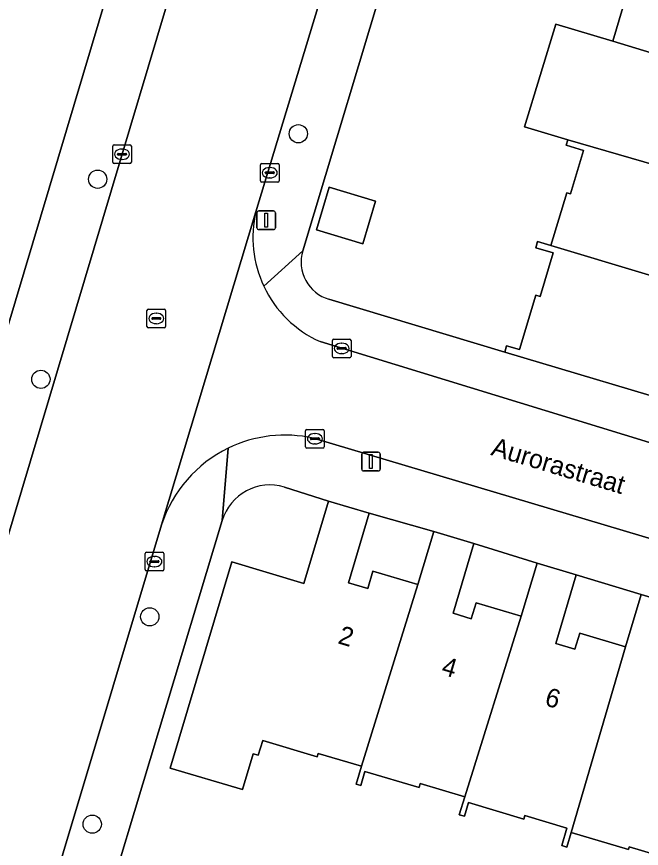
# Model space of a CAD drawing. Extents: x 162184 to 163154, y 385507 to 386516.
# Drawn here: x 162544.83 to 162578.31, y 386044.74 to 386089.33 of the extents above; entities that cross this region are included whole.
import ezdxf

# ---------------------------------------------------------------- set-up
doc = ezdxf.new("R2010")
doc.units = 0
for name, color, linetype in [('IMGEO_Boom', 7, 'Continuous'), ('IMGEO_Erf', 7, 'Continuous'), ('IMGEO_Groenvoorziening', 7, 'Continuous'), ('IMGEO_Kolk', 7, 'Continuous'), ('IMGEO_Lichtmast', 7, 'Continuous'), ('IMGEO_Openbare_ruimte_label', 7, 'Continuous'), ('IMGEO_Pand', 7, 'Continuous'), ('IMGEO_Pand_nummerreeks', 7, 'Continuous'), ('IMGEO_Rijbaan_lokaal_gesloten', 7, 'Continuous'), ('IMGEO_Rijbaan_lokaal_open', 7, 'Continuous'), ('IMGEO_Rioolput', 7, 'Continuous'), ('IMGEO_Voetpad_open', 7, 'Continuous')]:
    doc.layers.add(name, color=color, linetype=linetype)

msp = doc.modelspace()

# ---------------------------------------------------------------- linework, layer by layer
at = {"layer": 'IMGEO_Boom'}
for centre in [(162559.923, 386083.051), (162549.169, 386080.614), (162546.127, 386069.889), (162551.963, 386057.155), (162548.879, 386046.038)]:
    msp.add_circle(centre, 0.489, dxfattribs=at)
at = {"layer": 'IMGEO_Erf'}
for points in [[(162574.588, 386124.721), (162560.164, 386076.774)], [(162561.564, 386074.178), (162570.985, 386071.35), (162571.086, 386071.69), (162571.785, 386071.481), (162572.658, 386074.403), (162572.883, 386074.335), (162573.577, 386076.659), (162572.647, 386076.937), (162572.749, 386077.279), (162573.464, 386077.066), (162574.309, 386079.892), (162574.519, 386079.829), (162575.214, 386082.154), (162574.286, 386082.432), (162574.373, 386082.723), (162572.052, 386083.416), (162573.719, 386088.923), (162576.772, 386088.011), (162577.661, 386090.987)], [(162579.822, 386044.188), (162577.661, 386044.833), (162577.614, 386044.676), (162574.55, 386045.591), (162574.316, 386044.81), (162574.043, 386044.892), (162574.323, 386045.829), (162572.071, 386046.501), (162572.015, 386046.314), (162569.041, 386047.202), (162568.822, 386046.467), (162568.552, 386046.548), (162568.84, 386047.513), (162566.462, 386048.224), (162566.397, 386048.005), (162563.496, 386048.871), (162563.267, 386048.105), (162563.022, 386048.178), (162563.309, 386049.141), (162560.986, 386049.835), (162560.931, 386049.653), (162558.014, 386050.525), (162557.779, 386049.736), (162557.501, 386049.819), (162556.925, 386047.891), (162553.064, 386049.045), (162556.367, 386060.102), (162560.228, 386058.948), (162561.544, 386063.355), (162559.189, 386064.113)], [(162555.845, 386062.31), (162549.021, 386039.652), (162548.964, 386039.426), (162548.927, 386039.196), (162548.911, 386038.964), (162548.916, 386038.731), (162548.942, 386038.499), (162548.988, 386038.271), (162549.054, 386038.048), (162549.14, 386037.831), (162549.245, 386037.623), (162549.369, 386037.426), (162549.509, 386037.24), (162549.665, 386037.067), (162549.837, 386036.909), (162550.021, 386036.767), (162550.218, 386036.642), (162550.425, 386036.536), (162550.64, 386036.448), (162550.863, 386036.379), (162550.925, 386036.364), (162601.617, 386024.622)]]:
    msp.add_lwpolyline(points, dxfattribs=at)
for points in [[(162563.38, 386077.154), (162560.899, 386077.895), (162561.583, 386080.183), (162564.063, 386079.442)], [(162563.726, 386062.704), (162562.615, 386058.983), (162563.646, 386058.675), (162563.925, 386059.608), (162566.334, 386058.888), (162567.184, 386061.729)], [(162569.337, 386061.086), (162568.22, 386057.344), (162569.191, 386057.054), (162569.447, 386057.91), (162571.874, 386057.185), (162572.722, 386060.027)], [(162574.821, 386059.4), (162573.725, 386055.732), (162574.748, 386055.426), (162575.003, 386056.28), (162577.455, 386055.547), (162578.295, 386058.358)]]:
    msp.add_lwpolyline(points, close=True, dxfattribs=at)
for centre, radius, start, end in [((162562.154, 386076.172), 2.079, 163.1674, 253.5078), ((162558.42, 386061.536), 2.689, 73.3908, 163.274)]:
    msp.add_arc(centre, radius, start, end, dxfattribs=at)
at = {"layer": 'IMGEO_Groenvoorziening'}
msp.add_lwpolyline([(162540.262, 386059.084), (162551.525, 386096.722), (162551.592, 386096.979), (162551.635, 386097.241), (162551.656, 386097.506), (162551.652, 386097.772), (162551.624, 386098.036), (162551.573, 386098.297), (162551.499, 386098.552), (162551.403, 386098.8), (162551.285, 386099.038), (162551.146, 386099.264), (162550.987, 386099.477), (162550.81, 386099.675), (162550.616, 386099.857), (162550.406, 386100.02), (162550.183, 386100.164), (162549.948, 386100.288), (162549.702, 386100.39), (162549.449, 386100.47), (162549.189, 386100.526), (162549.072, 386100.544), (162535.156, 386102.359)], dxfattribs=at)
at = {"layer": 'IMGEO_Kolk'}
for p, q in [((162550.051, 386082.453), (162550.903, 386082.453)), ((162549.976, 386081.527), (162549.976, 386082.379)), ((162550.464, 386082.233), (162550.489, 386082.233)), ((162550.977, 386082.379), (162550.977, 386081.527)), ((162550.235, 386081.947), (162550.235, 386081.959)), ((162550.673, 386081.91), (162550.275, 386081.91)), ((162550.278, 386081.996), (162550.676, 386081.996)), ((162550.487, 386081.673), (162550.462, 386081.673)), ((162550.719, 386081.959), (162550.719, 386081.947)), ((162550.903, 386081.453), (162550.051, 386081.453)), ((162557.895, 386080.534), (162557.895, 386081.386)), ((162557.97, 386081.46), (162558.822, 386081.46)), ((162558.383, 386081.24), (162558.408, 386081.24)), ((162558.896, 386081.386), (162558.896, 386080.534)), ((162558.154, 386080.954), (162558.154, 386080.966)), ((162558.592, 386080.917), (162558.194, 386080.917)), ((162558.197, 386081.003), (162558.595, 386081.003)), ((162558.406, 386080.68), (162558.381, 386080.68)), ((162558.638, 386080.966), (162558.638, 386080.954)), ((162558.822, 386080.46), (162557.97, 386080.46)), ((162561.749, 386071.119), (162561.749, 386071.971)), ((162561.824, 386072.045), (162562.676, 386072.045)), ((162562.237, 386071.825), (162562.262, 386071.825)), ((162562.75, 386071.971), (162562.75, 386071.119)), ((162562.008, 386071.539), (162562.008, 386071.551)), ((162562.446, 386071.502), (162562.048, 386071.502)), ((162562.051, 386071.588), (162562.449, 386071.588)), ((162562.492, 386071.551), (162562.492, 386071.539)), ((162562.676, 386071.045), (162561.824, 386071.045)), ((162562.26, 386071.265), (162562.235, 386071.265)), ((162560.311, 386066.276), (162560.311, 386067.128)), ((162560.386, 386067.202), (162561.238, 386067.202)), ((162560.799, 386066.982), (162560.824, 386066.982)), ((162561.312, 386067.128), (162561.312, 386066.276)), ((162560.57, 386066.696), (162560.57, 386066.708)), ((162561.008, 386066.659), (162560.61, 386066.659)), ((162560.613, 386066.745), (162561.011, 386066.745)), ((162560.822, 386066.422), (162560.797, 386066.422)), ((162561.054, 386066.708), (162561.054, 386066.696)), ((162561.238, 386066.202), (162560.386, 386066.202)), ((162551.789, 386060.615), (162552.641, 386060.615)), ((162551.714, 386059.689), (162551.714, 386060.541)), ((162552.016, 386060.158), (162552.414, 386060.158)), ((162552.202, 386060.395), (162552.227, 386060.395)), ((162552.715, 386060.541), (162552.715, 386059.689)), ((162551.973, 386060.109), (162551.973, 386060.121)), ((162552.411, 386060.072), (162552.013, 386060.072)), ((162552.225, 386059.835), (162552.2, 386059.835)), ((162552.457, 386060.121), (162552.457, 386060.109)), ((162552.641, 386059.615), (162551.789, 386059.615))]:
    msp.add_line(p, q, dxfattribs=at)
for points in [[(162550.051, 386082.453), (162550.903, 386082.453)], [(162549.976, 386081.527), (162549.976, 386082.379)], [(162550.977, 386082.379), (162550.977, 386081.527)], [(162550.903, 386081.453), (162550.051, 386081.453)], [(162557.895, 386080.534), (162557.895, 386081.386)], [(162557.97, 386081.46), (162558.822, 386081.46)], [(162558.896, 386081.386), (162558.896, 386080.534)], [(162558.822, 386080.46), (162557.97, 386080.46)], [(162561.749, 386071.119), (162561.749, 386071.971)], [(162561.824, 386072.045), (162562.676, 386072.045)], [(162562.75, 386071.971), (162562.75, 386071.119)], [(162562.676, 386071.045), (162561.824, 386071.045)], [(162560.311, 386066.276), (162560.311, 386067.128)], [(162560.386, 386067.202), (162561.238, 386067.202)], [(162561.312, 386067.128), (162561.312, 386066.276)], [(162561.238, 386066.202), (162560.386, 386066.202)], [(162551.789, 386060.615), (162552.641, 386060.615)], [(162551.714, 386059.689), (162551.714, 386060.541)], [(162552.715, 386060.541), (162552.715, 386059.689)], [(162552.641, 386059.615), (162551.789, 386059.615)]]:
    msp.add_lwpolyline(points, dxfattribs=at)
for centre, radius, start, end in [((162550.053, 386082.377), 0.0765, 91.552, 178.448), ((162550.053, 386082.377), 0.0765, 91.552, 178.448), ((162550.901, 386082.377), 0.0765, 1.552, 88.448), ((162550.901, 386082.377), 0.0765, 1.552, 88.448), ((162550.275, 386081.956), 0.0403, 85.8775, 175.7526), ((162550.272, 386081.946), 0.0366, 178.938, 274.7102), ((162550.676, 386081.953), 0.043, 264.8664, 352.4533), ((162550.68, 386081.958), 0.0386, 1.7309, 96.639), ((162550.053, 386081.529), 0.0765, 181.552, 268.448), ((162550.053, 386081.529), 0.0765, 181.552, 268.448), ((162550.901, 386081.529), 0.0765, 271.552, 358.448), ((162550.901, 386081.529), 0.0765, 271.552, 358.448), ((162557.972, 386081.384), 0.0765, 91.552, 178.448), ((162557.972, 386081.384), 0.0765, 91.552, 178.448), ((162558.82, 386081.384), 0.0765, 1.552, 88.448), ((162558.82, 386081.384), 0.0765, 1.552, 88.448), ((162558.194, 386080.963), 0.0403, 85.8775, 175.7526), ((162558.191, 386080.953), 0.0366, 178.938, 274.7102), ((162558.595, 386080.96), 0.043, 264.8664, 352.4533), ((162558.599, 386080.965), 0.0386, 1.7309, 96.639), ((162557.972, 386080.536), 0.0765, 181.552, 268.448), ((162557.972, 386080.536), 0.0765, 181.552, 268.448), ((162558.82, 386080.536), 0.0765, 271.552, 358.448), ((162558.82, 386080.536), 0.0765, 271.552, 358.448), ((162561.826, 386071.969), 0.0765, 91.552, 178.448), ((162561.826, 386071.969), 0.0765, 91.552, 178.448), ((162562.674, 386071.969), 0.0765, 1.552, 88.448), ((162562.674, 386071.969), 0.0765, 1.552, 88.448), ((162562.048, 386071.548), 0.0403, 85.8775, 175.7526), ((162562.045, 386071.538), 0.0366, 178.938, 274.7102), ((162562.449, 386071.545), 0.043, 264.8664, 352.4533), ((162562.453, 386071.55), 0.0386, 1.7309, 96.639), ((162561.826, 386071.121), 0.0765, 181.552, 268.448), ((162561.826, 386071.121), 0.0765, 181.552, 268.448), ((162562.674, 386071.121), 0.0765, 271.552, 358.448), ((162562.674, 386071.121), 0.0765, 271.552, 358.448), ((162560.388, 386067.126), 0.0765, 91.552, 178.448), ((162560.388, 386067.126), 0.0765, 91.552, 178.448), ((162561.236, 386067.126), 0.0765, 1.552, 88.448), ((162561.236, 386067.126), 0.0765, 1.552, 88.448), ((162560.61, 386066.705), 0.0403, 85.8775, 175.7526), ((162560.607, 386066.695), 0.0366, 178.938, 274.7102), ((162561.011, 386066.702), 0.043, 264.8664, 352.4533), ((162561.015, 386066.707), 0.0386, 1.7309, 96.639), ((162560.388, 386066.278), 0.0765, 181.552, 268.448), ((162560.388, 386066.278), 0.0765, 181.552, 268.448), ((162561.236, 386066.278), 0.0765, 271.552, 358.448), ((162561.236, 386066.278), 0.0765, 271.552, 358.448), ((162551.791, 386060.539), 0.0765, 91.552, 178.448), ((162551.791, 386060.539), 0.0765, 91.552, 178.448), ((162552.639, 386060.539), 0.0765, 1.552, 88.448), ((162552.639, 386060.539), 0.0765, 1.552, 88.448), ((162552.013, 386060.118), 0.0403, 85.8775, 175.7526), ((162552.418, 386060.12), 0.0386, 1.7309, 96.639), ((162552.01, 386060.108), 0.0366, 178.938, 274.7102), ((162552.414, 386060.115), 0.043, 264.8664, 352.4533), ((162551.791, 386059.691), 0.0765, 181.552, 268.448), ((162551.791, 386059.691), 0.0765, 181.552, 268.448), ((162552.639, 386059.691), 0.0765, 271.552, 358.448), ((162552.639, 386059.691), 0.0765, 271.552, 358.448)]:
    msp.add_arc(centre, radius, start, end, dxfattribs=at)
for centre, major_axis, ratio, start_param, end_param in [((162550.463, 386081.953), (-0.387, 0.002), 0.722429, 4.712389, 7.853982), ((162550.488, 386081.953), (-0.39, 0.002), 0.717154, 1.570796, 4.712389), ((162558.382, 386080.96), (-0.387, 0.002), 0.722429, 4.712389, 7.853982), ((162558.407, 386080.96), (-0.39, 0.002), 0.717154, 1.570796, 4.712389), ((162562.236, 386071.545), (-0.387, 0.002), 0.722429, 4.712389, 7.853982), ((162562.261, 386071.545), (-0.39, 0.002), 0.717154, 1.570796, 4.712389), ((162560.798, 386066.702), (-0.387, 0.002), 0.722429, 4.712389, 7.853982), ((162560.823, 386066.702), (-0.39, 0.002), 0.717154, 1.570796, 4.712389), ((162552.201, 386060.115), (-0.387, 0.002), 0.722429, 4.712389, 7.853982), ((162552.226, 386060.115), (-0.39, 0.002), 0.717154, 1.570796, 4.712389)]:
    msp.add_ellipse(centre, major_axis=major_axis, ratio=ratio, start_param=start_param, end_param=end_param, dxfattribs=at)
at = {"layer": 'IMGEO_Lichtmast'}
for p, q in [((162557.807, 386078.913), (162558.597, 386078.913)), ((162558.597, 386078.913), (162557.807, 386078.913)), ((162557.707, 386078.013), (162557.707, 386078.813)), ((162557.707, 386078.813), (162557.707, 386078.013)), ((162558.697, 386078.813), (162558.697, 386078.013)), ((162558.697, 386078.013), (162558.697, 386078.813)), ((162558.597, 386077.913), (162557.807, 386077.913)), ((162557.807, 386077.913), (162558.597, 386077.913)), ((162563.42, 386065.973), (162564.21, 386065.973)), ((162564.21, 386065.973), (162563.42, 386065.973)), ((162563.32, 386065.073), (162563.32, 386065.873)), ((162563.32, 386065.873), (162563.32, 386065.073)), ((162564.31, 386065.873), (162564.31, 386065.073)), ((162564.31, 386065.073), (162564.31, 386065.873)), ((162564.21, 386064.973), (162563.42, 386064.973)), ((162563.42, 386064.973), (162564.21, 386064.973))]:
    msp.add_line(p, q, dxfattribs=at)
for points in [[(162558.127, 386078.788), (162558.277, 386078.788), (162558.277, 386078.038), (162558.127, 386078.038), (162558.127, 386078.788)], [(162563.74, 386065.848), (162563.89, 386065.848), (162563.89, 386065.098), (162563.74, 386065.098), (162563.74, 386065.848)]]:
    msp.add_lwpolyline(points, dxfattribs=at)
for centre, start, end in [((162557.807, 386078.813), 90, 180), ((162557.807, 386078.813), 90, 180), ((162558.597, 386078.813), 0, 90), ((162558.597, 386078.813), 360, 90), ((162557.807, 386078.013), 180, 270), ((162557.807, 386078.013), 180, 270), ((162558.597, 386078.013), 270, 0), ((162558.597, 386078.013), 270, 0), ((162563.42, 386065.873), 90, 180), ((162563.42, 386065.873), 90, 180), ((162564.21, 386065.873), 0, 90), ((162564.21, 386065.873), 360, 90), ((162563.42, 386065.073), 180, 270), ((162563.42, 386065.073), 180, 270), ((162564.21, 386065.073), 270, 0), ((162564.21, 386065.073), 270, 0)]:
    msp.add_arc(centre, 0.1, start, end, dxfattribs=at)
at = {"layer": 'IMGEO_Pand'}
for points in [[(162591.23, 386089.684), (162588.386, 386090.535), (162577.712, 386093.701), (162577.629, 386093.423), (162578.556, 386093.146), (162577.89, 386090.918), (162577.661, 386090.987), (162576.772, 386088.011), (162586.695, 386085), (162587.392, 386087.335), (162586.606, 386087.57), (162586.941, 386088.691), (162590.607, 386087.596)], [(162585.106, 386079.616), (162585.771, 386081.84), (162584.938, 386082.089), (162585.269, 386083.197), (162588.93, 386082.104), (162589.541, 386084.15), (162586.695, 386085), (162576.772, 386088.011), (162573.719, 386088.923), (162572.052, 386083.416), (162574.373, 386082.723)], [(162573.464, 386077.066), (162583.387, 386074.069), (162584.081, 386076.39), (162583.306, 386076.621), (162583.617, 386077.664), (162587.259, 386076.576), (162587.916, 386078.777), (162585.106, 386079.616), (162574.373, 386082.723), (162574.286, 386082.432), (162575.214, 386082.154), (162574.519, 386079.829), (162574.309, 386079.892)], [(162563.38, 386077.154), (162564.063, 386079.442), (162561.583, 386080.183), (162560.899, 386077.895)], [(162581.66, 386068.161), (162582.467, 386070.862), (162581.62, 386071.115), (162581.944, 386072.201), (162585.655, 386071.093), (162586.285, 386073.202), (162583.387, 386074.069), (162573.464, 386077.066), (162572.749, 386077.279), (162572.647, 386076.937), (162573.577, 386076.659), (162572.883, 386074.335), (162572.658, 386074.403), (162571.785, 386071.481), (162571.086, 386071.69), (162570.985, 386071.35)], [(162561.544, 386063.355), (162560.228, 386058.948), (162556.367, 386060.102), (162553.064, 386049.045), (162556.925, 386047.891), (162557.501, 386049.819), (162557.779, 386049.736), (162558.014, 386050.525), (162560.931, 386049.653), (162560.986, 386049.835), (162563.309, 386049.141), (162566.334, 386058.888), (162563.925, 386059.608), (162563.646, 386058.675), (162562.615, 386058.983), (162563.726, 386062.704)], [(162567.184, 386061.729), (162566.334, 386058.888), (162563.309, 386049.141), (162563.022, 386048.178), (162563.267, 386048.105), (162563.496, 386048.871), (162566.397, 386048.005), (162566.462, 386048.224), (162568.84, 386047.513), (162571.874, 386057.185), (162569.447, 386057.91), (162569.191, 386057.054), (162568.22, 386057.344), (162569.337, 386061.086)], [(162572.722, 386060.027), (162571.874, 386057.185), (162568.84, 386047.513), (162568.552, 386046.548), (162568.822, 386046.467), (162569.041, 386047.202), (162572.015, 386046.314), (162572.071, 386046.501), (162574.323, 386045.829), (162574.043, 386044.892), (162574.316, 386044.81), (162574.55, 386045.591), (162577.455, 386055.547), (162575.003, 386056.28), (162574.748, 386055.426), (162573.725, 386055.732), (162574.821, 386059.4)], [(162578.295, 386058.358), (162577.455, 386055.547), (162574.55, 386045.591), (162577.614, 386044.676), (162577.661, 386044.833), (162579.822, 386044.188), (162579.543, 386043.254), (162579.831, 386043.168), (162580.055, 386043.914), (162582.959, 386053.892), (162580.522, 386054.62), (162580.266, 386053.764), (162579.284, 386054.057), (162580.383, 386057.735)]]:
    msp.add_lwpolyline(points, close=True, dxfattribs=at)
at = {"layer": 'IMGEO_Rijbaan_lokaal_gesloten'}
msp.add_lwpolyline([(162544.709, 386035.795), (162552.598, 386062.092), (162557.647, 386078.873), (162571.767, 386125.417), (162571.839, 386125.681), (162564.246, 386127.991), (162564.122, 386127.569), (162562.109, 386120.842), (162561.946, 386119.898), (162556.224, 386101.164), (162536.876, 386036.467)], dxfattribs=at)
at = {"layer": 'IMGEO_Rijbaan_lokaal_open'}
for points in [[(162560.731, 386066.727), (162603.581, 386053.947), (162603.688, 386053.915), (162605.048, 386058.656), (162605.917, 386061.573), (162606.785, 386064.491), (162607.654, 386067.409), (162608.523, 386070.326), (162609.391, 386073.244), (162610.26, 386076.162), (162611.129, 386079.08), (162608.061, 386079.862), (162604.547, 386080.902), (162599.342, 386063.317), (162593.178, 386065.153), (162593.091, 386064.863)], [(162557.647, 386078.873), (162552.598, 386062.092)], [(162589.849, 386063.116), (162586.781, 386064.034), (162561.09, 386071.908)]]:
    msp.add_lwpolyline(points, dxfattribs=at)
for centre, radius, start, end in [((162563.605, 386077.487), 6.117, 166.9011, 205.2215), ((162563.612, 386077.489), 6.125, 205.2156, 245.6834), ((162559.209, 386059.95), 6.946, 77.3395, 115.9796), ((162559.208, 386059.945), 6.95, 115.9596, 162.0057)]:
    msp.add_arc(centre, radius, start, end, dxfattribs=at)
at = {"layer": 'IMGEO_Rioolput'}
for p, q in [((162551.812, 386072.724), (162551.812, 386073.576)), ((162551.887, 386073.65), (162552.739, 386073.65)), ((162552.813, 386073.576), (162552.813, 386072.724)), ((162552.071, 386073.144), (162552.071, 386073.156)), ((162552.509, 386073.107), (162552.111, 386073.107)), ((162552.114, 386073.193), (162552.512, 386073.193)), ((162552.3, 386073.43), (162552.325, 386073.43)), ((162552.555, 386073.156), (162552.555, 386073.144)), ((162552.739, 386072.65), (162551.887, 386072.65)), ((162552.323, 386072.87), (162552.298, 386072.87))]:
    msp.add_line(p, q, dxfattribs=at)
for points in [[(162551.812, 386072.724), (162551.812, 386073.576)], [(162551.887, 386073.65), (162552.739, 386073.65)], [(162552.813, 386073.576), (162552.813, 386072.724)], [(162552.739, 386072.65), (162551.887, 386072.65)]]:
    msp.add_lwpolyline(points, dxfattribs=at)
for centre, radius, start, end in [((162551.889, 386073.574), 0.0765, 91.552, 178.448), ((162551.889, 386073.574), 0.0765, 91.552, 178.448), ((162552.737, 386073.574), 0.0765, 1.552, 88.448), ((162552.737, 386073.574), 0.0765, 1.552, 88.448), ((162552.111, 386073.153), 0.0403, 85.8775, 175.7526), ((162552.108, 386073.143), 0.0366, 178.938, 274.7102), ((162552.512, 386073.15), 0.043, 264.8664, 352.4533), ((162552.516, 386073.155), 0.0386, 1.7309, 96.639), ((162551.889, 386072.726), 0.0765, 181.552, 268.448), ((162551.889, 386072.726), 0.0765, 181.552, 268.448), ((162552.737, 386072.726), 0.0765, 271.552, 358.448), ((162552.737, 386072.726), 0.0765, 271.552, 358.448)]:
    msp.add_arc(centre, radius, start, end, dxfattribs=at)
for centre, major_axis, ratio, start_param, end_param in [((162552.299, 386073.15), (-0.387, 0.002), 0.722429, 4.712389, 7.853982), ((162552.324, 386073.15), (-0.39, 0.002), 0.717154, 1.570796, 4.712389)]:
    msp.add_ellipse(centre, major_axis=major_axis, ratio=ratio, start_param=start_param, end_param=end_param, dxfattribs=at)
at = {"layer": 'IMGEO_Voetpad_open'}
for points in [[(162571.839, 386125.681), (162571.767, 386125.417), (162557.647, 386078.873)], [(162558.071, 386074.88), (162560.164, 386076.774), (162574.588, 386124.721)], [(162556.224, 386101.164), (162556.315, 386101.699), (162556.358, 386102.24), (162556.352, 386102.783), (162556.298, 386103.323), (162556.196, 386103.857), (162556.047, 386104.378), (162555.851, 386104.885), (162555.611, 386105.372), (162555.329, 386105.836), (162555.006, 386106.272), (162554.646, 386106.678), (162551.525, 386096.722), (162540.262, 386059.084), (162535.28, 386042.436), (162535.249, 386042.291), (162532.94, 386034.869)], [(162536.876, 386036.467), (162556.224, 386101.164)], [(162591.23, 386089.684), (162590.607, 386087.596), (162589.541, 386084.15), (162588.93, 386082.104), (162587.916, 386078.777), (162587.259, 386076.576), (162586.285, 386073.202), (162585.655, 386071.093), (162584.448, 386067.313), (162581.66, 386068.161), (162570.985, 386071.35), (162561.564, 386074.178)], [(162561.09, 386071.908), (162586.781, 386064.034), (162594.025, 386088.092)], [(162560.164, 386076.774), (162558.071, 386074.88)], [(162603.581, 386053.947), (162560.731, 386066.727)], [(162548.927, 386039.196), (162548.964, 386039.426), (162549.021, 386039.652), (162555.845, 386062.31), (162556.166, 386066.194)], [(162556.166, 386066.194), (162555.845, 386062.31)], [(162559.189, 386064.113), (162561.544, 386063.355), (162563.726, 386062.704), (162567.184, 386061.729), (162569.337, 386061.086), (162572.722, 386060.027), (162574.821, 386059.4), (162578.295, 386058.358), (162580.383, 386057.735), (162583.807, 386056.731), (162585.894, 386056.108), (162589.404, 386055.065), (162591.485, 386054.443), (162594.863, 386053.439), (162596.978, 386052.808)], [(162552.598, 386062.092), (162544.709, 386035.795)]]:
    msp.add_lwpolyline(points, dxfattribs=at)
for centre, radius, start, end in [((162563.605, 386077.487), 6.117, 166.9011, 205.2215), ((162562.154, 386076.172), 2.079, 163.1674, 253.5078), ((162563.612, 386077.489), 6.125, 205.2156, 245.6834), ((162559.209, 386059.95), 6.946, 77.3395, 115.9796), ((162559.208, 386059.945), 6.95, 115.9596, 162.0057), ((162558.42, 386061.536), 2.689, 73.3908, 163.274)]:
    msp.add_arc(centre, radius, start, end, dxfattribs=at)

# ---------------------------------------------------------------- texts
at = {"layer": 'IMGEO_Openbare_ruimte_label'}
msp.add_text('Aurorastraat', height=1, rotation=343.3227, dxfattribs=at).set_placement((162570.197, 386065.839))
at = {"layer": 'IMGEO_Pand_nummerreeks'}
for s, p in [('2', (162561.996, 386055.744)), ('4', (162567.537, 386054.087)), ('6', (162573.076, 386052.429))]:
    msp.add_text(s, height=1, rotation=343.3413, dxfattribs=at).set_placement(p)

doc.saveas('drawing.dxf')
